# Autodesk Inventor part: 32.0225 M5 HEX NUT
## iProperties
Created: 2012-10
Part Number: 32.0225 M5 HEX NUT
Document SubType Name: Modeling
Designer: Administrator
Density: 7.85 g/cm^3
Material: Steel
Mass: 1.31017 g
Surface Area: 2.41612 cm^2
Volume: 0.166901 cm^3
Author: Administrator
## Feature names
1. Base1
2. Hole1
